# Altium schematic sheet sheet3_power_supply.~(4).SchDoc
size A3; SheetNumber: 3; SheetTotal: 4
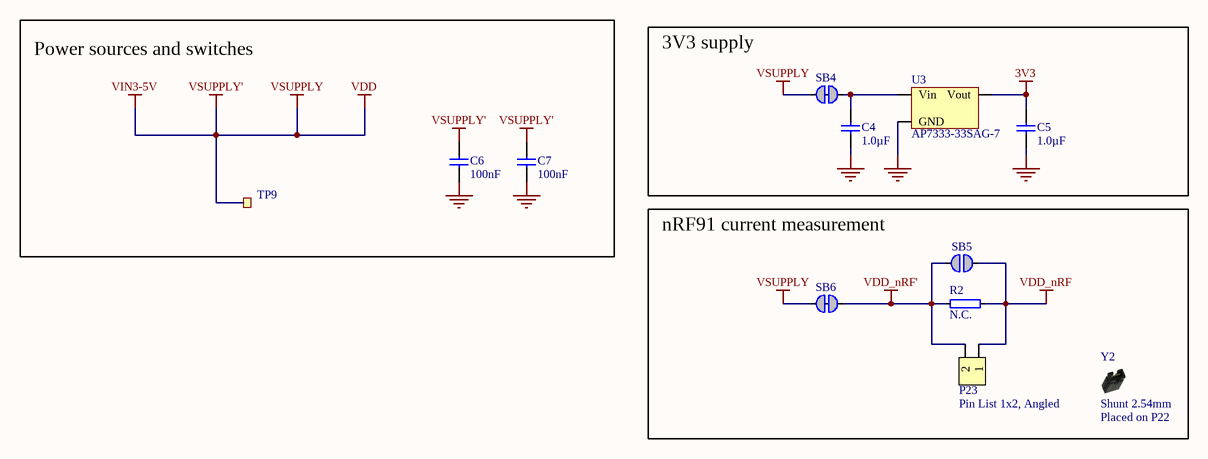
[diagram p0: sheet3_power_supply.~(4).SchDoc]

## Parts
C4  1.0µF  [CAPC0603X03L_C]
C5  1.0µF  [CAPC0603X03L_C]
C6  100nF  [CAPC0603X03L_C]
C7  100nF  [CAPC0603X03L_C]
P23  Pin List 1x2, Angled  [LIST_ANG_1x2-SMD-2.54MM]
R2  N.C.  [RESC1005X04L_NC]
SB4  Solderbridge  [Solderbridge_Shorted]  (value not drawn)  (net tie, no BOM)
SB5  Solderbridge  [Solderbridge]  (value not drawn)  (no BOM)
SB6  Solderbridge  [Solderbridge_Shorted_Power]  (value not drawn)  (net tie, no BOM)
TP9  Ø1.5mm,SMD  [TP_SMD_D1.5mm]  (value not drawn)  (no BOM)
U3  AP7333-33SAG-7  [SOT-23A]
Y2  Shunt 2.54mm  Assembly: Placed on P22  [Shunt_2.54mm_Horizontal]

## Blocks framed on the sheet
Power sources and switches: C6 C7 TP9
3V3 supply: C4 C5 SB4 U3
nRF91 current measurement: P23 R2 SB5 SB6 Y2

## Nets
3V3: C5.1 U3.2(Vout)
GND: C4.2 C5.2 C6.2 C7.1 U3.3(GND)
VDD: C6.1 C7.2 SB4.2 SB6.1 TP9.1  [also labelled VIN3-5V, VSUPPLY, VSUPPLY']
VDD_nRF: P23.1 R2.1 SB5.1
VDD_nRF': P23.2 R2.2 SB5.2 SB6.2
NetC4_1: C4.1 SB4.1 U3.1(Vin)

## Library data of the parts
C4 C5 = C0201-1µ0: Capacitor, X5R, ±10%; Manufacturer: N.A.; Part number IPS: 00000001723; Note: 10V; Pad Count: 2
C6 C7 = C0201-100n: Capacitor, X5R, ±10%; Manufacturer: N.A.; Part number IPS: 00000001248, 00000002505; Note: 16V; Pad Count: 2
P23 = Pin List Ang 1x2 SMD, 2.54mm: Pin List 1x2, 2.54mm (100mil), Right Angled, SMD; Manufacturer: W-CON; Manufacturer Part Number: 1125B-1102S0Z135R2; Part number IPS: 00000009972; Note: N.A.; Artikkelnr Noca: 55010023; Pad Count: 2
R2 = R0402-N.C.: Not mounted; Manufacturer: N.A.; Note: Chip Res; Assembly: Not mounted; Pad Count: 2
SB4 = Solderbridge Shorted: Shorted Solderbridge; Manufacturer: N.A.; Pad Count: 2
SB5 = Solderbridge: Manufacturer: N.A.; Pad Count: 2
SB6 = Solderbridge Shorted Power: Shorted Solderbridge Power; Manufacturer: N.A.; Pad Count: 2
TP9 = TP_SMD_Ø1.5MM: 1.5mm circular SMD testpad; Manufacturer: Nordic Semiconductor; Manufacturer Part Number: N.A.; Pad Count: 1
U3 = AP7333-33SAG-7: 300mA, Low Quiescent Current, Fast Transient Low Dropout Linear Regulator; Manufacturer: Diodes Incorporated; Part number IPS: 00000001673; Note: N.A.; Artikkelnr Noca: 17039216; Pad Count: 3
Y2 = SHUNT JUMPER 2.54mm BLACK GOLD Horizontal (Obsolete): Shunt Jumper 2.54mm Black; Manufacturer: N.A.; Part number IPS: 00000001916; Note: SHUNT JUMPER .1" BLACK GOLD, h=6.00mm, w=5.00mm; Artikkelnr Noca: 56099001; Pad Count: 2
